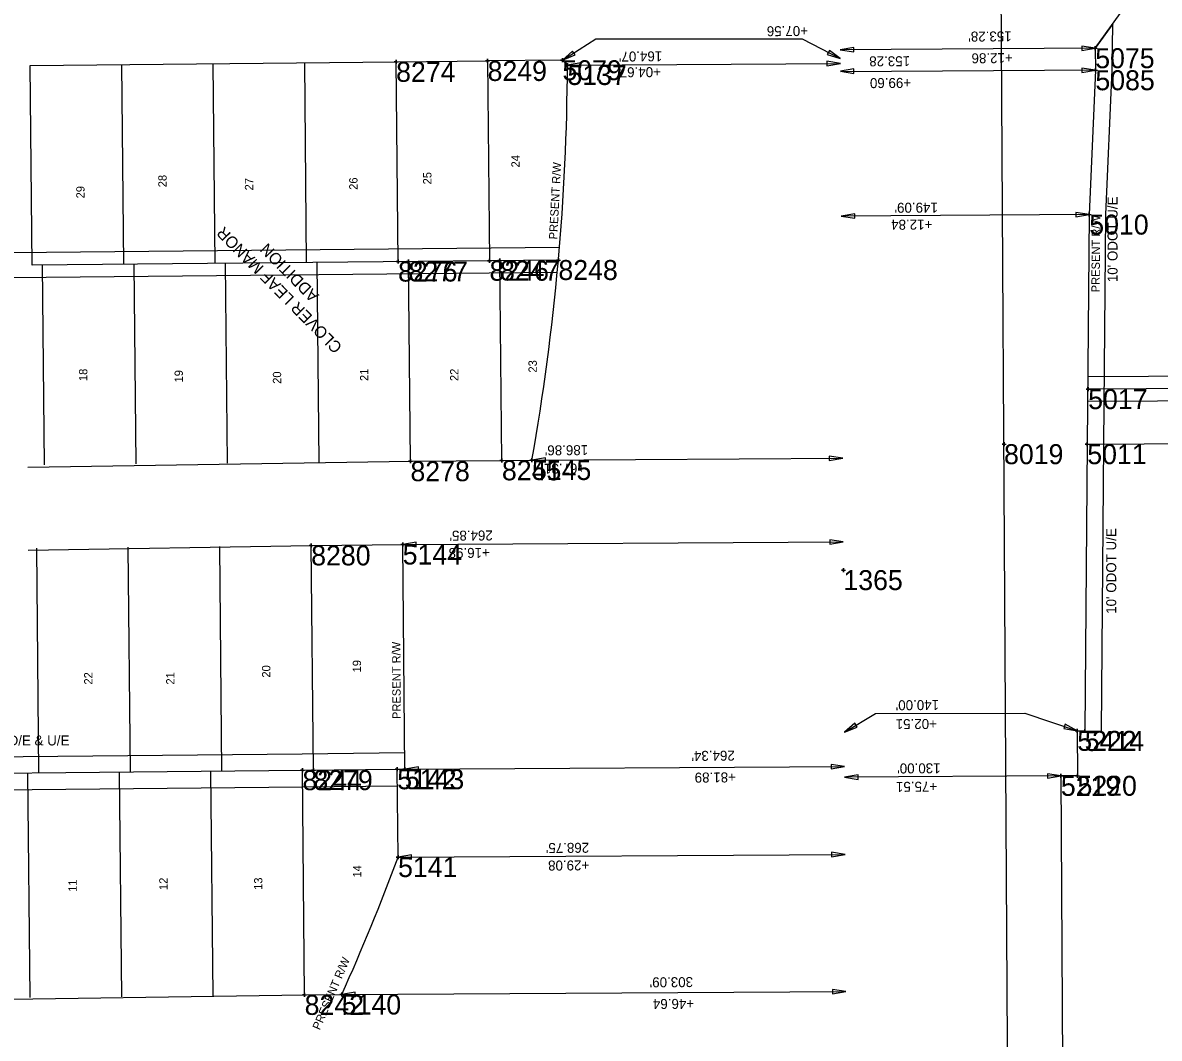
# Model space of a CAD drawing. Extents: x 2145146 to 2158053, y 137507 to 150829.
# Drawn here: x 2150322 to 2151005, y 144238 to 144848 of the extents above; entities that cross this region are included whole.
import ezdxf

# ---------------------------------------------------------------- set-up
doc = ezdxf.new("R2010")
doc.units = 0
for name, color, linetype in [('ALIGN_Cogo Points', 7, 'Continuous'), ('ALIGN_ROW Dimension', 7, 'Continuous'), ('ALIGN_ROW Line', 7, 'Continuous'), ('ALIGN_ROW Text', 7, 'Continuous'), ('PLSS_Block Line', 7, 'Continuous'), ('PLSS_Easement', 7, 'Continuous'), ('PLSS_Lot Line', 7, 'Continuous'), ('PLSS_Property Line', 7, 'Continuous'), ('PLSS_Section Line', 7, 'Continuous'), ('PLSS_Text', 7, 'Continuous'), ('PLSS_Text_TURNED OFF', 7, 'Continuous')]:
    doc.layers.add(name, color=color, linetype=linetype)

# ---------------------------------------------------------------- blocks, each defined once
blk = doc.blocks.new('Arrowhd')
at = {"layer": 'PLSS_Property Line'}
blk.add_lwpolyline([(0.125, -0.021), (0.125, 0.021), (0, 0)], close=True, dxfattribs=at)

msp = doc.modelspace()

# ---------------------------------------------------------------- linework, layer by layer
at = {"layer": 'ALIGN_Cogo Points'}
for points in [[(2150966.92, 144832.96), (2150966.92, 144834.16), (2150966.92, 144832.96), (2150965.72, 144832.96), (2150966.92, 144832.96), (2150966.92, 144831.76), (2150966.92, 144832.96), (2150968.12, 144832.96)], [(2150546.63, 144824.75), (2150546.63, 144825.95), (2150546.63, 144824.75), (2150545.43, 144824.75), (2150546.63, 144824.75), (2150546.63, 144823.55), (2150546.63, 144824.75), (2150547.83, 144824.75)], [(2150601.63, 144825.29), (2150601.63, 144826.49), (2150601.63, 144825.29), (2150600.43, 144825.29), (2150601.63, 144825.29), (2150601.63, 144824.09), (2150601.63, 144825.29), (2150602.83, 144825.29)], [(2150646.61, 144825.73), (2150646.61, 144826.93), (2150646.61, 144825.73), (2150645.41, 144825.73), (2150646.61, 144825.73), (2150646.61, 144824.53), (2150646.61, 144825.73), (2150647.81, 144825.73)], [(2150649.63, 144822.87), (2150649.63, 144824.07), (2150649.63, 144822.87), (2150648.43, 144822.87), (2150649.63, 144822.87), (2150649.63, 144821.67), (2150649.63, 144822.87), (2150650.83, 144822.87)], [(2150967.01, 144819.7), (2150967.01, 144820.9), (2150967.01, 144819.7), (2150965.81, 144819.7), (2150967.01, 144819.7), (2150967.01, 144818.5), (2150967.01, 144819.7), (2150968.21, 144819.7)], [(2150963.34, 144732.92), (2150963.34, 144734.12), (2150963.34, 144732.92), (2150962.14, 144732.92), (2150963.34, 144732.92), (2150963.34, 144731.72), (2150963.34, 144732.92), (2150964.54, 144732.92)], [(2150547.81, 144704.67), (2150547.81, 144705.87), (2150547.81, 144704.67), (2150546.61, 144704.67), (2150547.81, 144704.67), (2150547.81, 144703.47), (2150547.81, 144704.67), (2150549.01, 144704.67)], [(2150554.08, 144704.73), (2150554.08, 144705.93), (2150554.08, 144704.73), (2150552.88, 144704.73), (2150554.08, 144704.73), (2150554.08, 144703.53), (2150554.08, 144704.73), (2150555.28, 144704.73)], [(2150602.8, 144705.21), (2150602.8, 144706.41), (2150602.8, 144705.21), (2150601.6, 144705.21), (2150602.8, 144705.21), (2150602.8, 144704.01), (2150602.8, 144705.21), (2150604, 144705.21)], [(2150609.08, 144705.27), (2150609.08, 144706.47), (2150609.08, 144705.27), (2150607.88, 144705.27), (2150609.08, 144705.27), (2150609.08, 144704.07), (2150609.08, 144705.27), (2150610.28, 144705.27)], [(2150644.2, 144705.62), (2150644.2, 144706.82), (2150644.2, 144705.62), (2150643, 144705.62), (2150644.2, 144705.62), (2150644.2, 144704.42), (2150644.2, 144705.62), (2150645.4, 144705.62)], [(2150962.68, 144627.99), (2150962.68, 144629.19), (2150962.68, 144627.99), (2150961.48, 144627.99), (2150962.68, 144627.99), (2150962.68, 144626.79), (2150962.68, 144627.99), (2150963.88, 144627.99)], [(2150912.09, 144594.9), (2150912.09, 144596.1), (2150912.09, 144594.9), (2150910.89, 144594.9), (2150912.09, 144594.9), (2150912.09, 144593.7), (2150912.09, 144594.9), (2150913.29, 144594.9)], [(2150962.14, 144594.9), (2150962.14, 144596.1), (2150962.14, 144594.9), (2150960.94, 144594.9), (2150962.14, 144594.9), (2150962.14, 144593.7), (2150962.14, 144594.9), (2150963.34, 144594.9)], [(2150610.25, 144585.19), (2150610.25, 144586.39), (2150610.25, 144585.19), (2150609.05, 144585.19), (2150610.25, 144585.19), (2150610.25, 144583.99), (2150610.25, 144585.19), (2150611.45, 144585.19)], [(2150628.26, 144585.37), (2150628.26, 144586.57), (2150628.26, 144585.37), (2150627.06, 144585.37), (2150628.26, 144585.37), (2150628.26, 144584.17), (2150628.26, 144585.37), (2150629.46, 144585.37)], [(2150555.25, 144584.65), (2150555.25, 144585.85), (2150555.25, 144584.65), (2150554.05, 144584.65), (2150555.25, 144584.65), (2150555.25, 144583.45), (2150555.25, 144584.65), (2150556.45, 144584.65)], [(2150495.58, 144534.03), (2150495.58, 144535.23), (2150495.58, 144534.03), (2150494.38, 144534.03), (2150495.58, 144534.03), (2150495.58, 144532.83), (2150495.58, 144534.03), (2150496.78, 144534.03)], [(2150550.58, 144534.57), (2150550.58, 144535.77), (2150550.58, 144534.57), (2150549.38, 144534.57), (2150550.58, 144534.57), (2150550.58, 144533.37), (2150550.58, 144534.57), (2150551.78, 144534.57)], [(2150815.53, 144519.19), (2150815.53, 144520.39), (2150815.53, 144519.19), (2150814.33, 144519.19), (2150815.53, 144519.19), (2150815.53, 144517.99), (2150815.53, 144519.19), (2150816.73, 144519.19)], [(2150956.11, 144422.54), (2150956.11, 144423.74), (2150956.11, 144422.54), (2150954.91, 144422.54), (2150956.11, 144422.54), (2150956.11, 144421.34), (2150956.11, 144422.54), (2150957.31, 144422.54)], [(2150960.63, 144422.47), (2150960.63, 144423.67), (2150960.63, 144422.47), (2150959.43, 144422.47), (2150960.63, 144422.47), (2150960.63, 144421.27), (2150960.63, 144422.47), (2150961.83, 144422.47)], [(2150490.32, 144398.88), (2150490.32, 144400.08), (2150490.32, 144398.88), (2150489.12, 144398.88), (2150490.32, 144398.88), (2150490.32, 144397.68), (2150490.32, 144398.88), (2150491.52, 144398.88)], [(2150496.9, 144398.94), (2150496.9, 144400.14), (2150496.9, 144398.94), (2150495.7, 144398.94), (2150496.9, 144398.94), (2150496.9, 144397.74), (2150496.9, 144398.94), (2150498.1, 144398.94)], [(2150547.29, 144399.44), (2150547.29, 144400.64), (2150547.29, 144399.44), (2150546.09, 144399.44), (2150547.29, 144399.44), (2150547.29, 144398.24), (2150547.29, 144399.44), (2150548.49, 144399.44)], [(2150551.9, 144399.48), (2150551.9, 144400.68), (2150551.9, 144399.48), (2150550.7, 144399.48), (2150551.9, 144399.48), (2150551.9, 144398.28), (2150551.9, 144399.48), (2150553.1, 144399.48)], [(2150946.27, 144395.48), (2150946.27, 144396.68), (2150946.27, 144395.48), (2150945.07, 144395.48), (2150946.27, 144395.48), (2150946.27, 144394.28), (2150946.27, 144395.48), (2150947.47, 144395.48)], [(2150956.27, 144395.54), (2150956.27, 144396.74), (2150956.27, 144395.54), (2150955.07, 144395.54), (2150956.27, 144395.54), (2150956.27, 144394.34), (2150956.27, 144395.54), (2150957.47, 144395.54)], [(2150547.81, 144346.65), (2150547.81, 144347.85), (2150547.81, 144346.65), (2150546.61, 144346.65), (2150547.81, 144346.65), (2150547.81, 144345.45), (2150547.81, 144346.65), (2150549.01, 144346.65)], [(2150491.64, 144263.79), (2150491.64, 144264.99), (2150491.64, 144263.79), (2150490.44, 144263.79), (2150491.64, 144263.79), (2150491.64, 144262.59), (2150491.64, 144263.79), (2150492.84, 144263.79)], [(2150513.97, 144264.01), (2150513.97, 144265.21), (2150513.97, 144264.01), (2150512.77, 144264.01), (2150513.97, 144264.01), (2150513.97, 144262.81), (2150513.97, 144264.01), (2150515.17, 144264.01)]]:
    msp.add_lwpolyline(points, dxfattribs=at)
at = {"layer": 'ALIGN_ROW Dimension'}
for points in [[(2150646.61, 144825.73), (2150666.76, 144838.62), (2150790.78, 144838.62)], [(2150790.78, 144838.62), (2150813.68, 144826.73)], [(2150966.92, 144832.96), (2150813.65, 144832.04)], [(2150649.63, 144822.87), (2150813.7, 144823.85)], [(2150967.01, 144819.7), (2150813.73, 144818.78)], [(2150963.34, 144732.92), (2150814.25, 144732.02)], [(2150628.26, 144585.35), (2150815.12, 144586.47)], [(2150550.59, 144534.57), (2150815.43, 144536.16)], [(2150816.1, 144421.7), (2150834.77, 144433.03), (2150924.67, 144433.22), (2150956.11, 144422.54)], [(2150551.9, 144399.48), (2150816.24, 144401.07)], [(2150946.27, 144395.48), (2150816.28, 144394.69)], [(2150547.81, 144346.65), (2150816.56, 144348.27)], [(2150513.97, 144264.01), (2150817.05, 144265.83)]]:
    msp.add_lwpolyline(points, dxfattribs=at)
at = {"layer": 'ALIGN_ROW Line'}
for points in [[(2150966.92, 144832.96), (2150967.01, 144819.7), (2150963.34, 144732.92), (2150962.14, 144594.9), (2150960.63, 144422.47), (2150956.11, 144422.54), (2150956.27, 144395.54), (2150946.27, 144395.48), (2150947.31, 144222.48), (2150964.59, 144027.13), (2150968.98, 143967.36)], [(2150649.63, 144822.87), (2150646.61, 144825.73), (2150601.63, 144825.29)], [(2150610.25, 144585.19), (2150628.26, 144585.37)], [(2150547.81, 144346.65), (2150547.29, 144399.44), (2150551.9, 144399.48), (2150550.58, 144534.57)], [(2150491.64, 144263.79), (2150513.97, 144264.01)]]:
    msp.add_lwpolyline(points, dxfattribs=at)
for radius, start, end in [(1397.39, 349.964, 359.75306), (1382.39, 335.88153, 339.58352)]:
    msp.add_arc((2149252.26, 144828.89), radius, start, end, dxfattribs=at)
at = {"layer": 'PLSS_Block Line'}
for points in [[(2150326.69, 144822.6), (2150546.63, 144824.75), (2150601.63, 144825.29)], [(2150325.15, 144581.16), (2150555.25, 144584.65), (2150610.25, 144585.19), (2150628.26, 144585.35)], [(2150325.45, 144531.16), (2150495.6, 144534.03), (2150550.58, 144534.57)], [(2150273.6, 144260.64), (2150491.64, 144263.79), (2150513.97, 144264.01)]]:
    msp.add_lwpolyline(points, dxfattribs=at)
at = {"layer": 'PLSS_Easement'}
msp.add_lwpolyline([(2150960.63, 144422.47), (2150970.63, 144422.34), (2150972.14, 144594.95), (2150973.34, 144732.98), (2150977.02, 144819.89), (2150977.41, 144847.56), (2150966.92, 144832.96), (2150967.01, 144819.7), (2150963.34, 144732.92), (2150962.14, 144594.9)], close=True, dxfattribs=at)
for points in [[(2150644.84, 144713.12), (2150253.96, 144709.3)], [(2150643.51, 144698.11), (2150254.06, 144694.3)], [(2150966.29, 143960.36), (2151023.92, 143938.26), (2151215.08, 143953.41), (2151215.03, 144214.86), (2151144.43, 144295.52), (2151144.45, 144636.46), (2150962.64, 144635.49)], [(2150968.98, 143967.36), (2151025.02, 143945.87), (2151207.58, 143960.33), (2151207.53, 144212.04), (2151136.93, 144292.7), (2151136.95, 144628.92), (2150962.68, 144627.99)], [(2150971.66, 143974.36), (2151026.12, 143953.49), (2151200.08, 143967.26), (2151200.03, 144209.22), (2151129.43, 144289.88), (2151129.45, 144621.38), (2150962.72, 144620.49)], [(2149839.62, 144402.51), (2150490.22, 144408.84), (2150551.8, 144409.48)], [(2149839.81, 144382.51), (2150490.41, 144388.84), (2150547.39, 144389.44)]]:
    msp.add_lwpolyline(points, dxfattribs=at)
at = {"layer": 'PLSS_Lot Line'}
for points in [[(2150601.64, 144825.29), (2150602.8, 144705.21)], [(2150327.86, 144702.52), (2150326.69, 144822.6)], [(2150382.86, 144703.06), (2150381.68, 144823.14)], [(2150437.86, 144703.6), (2150436.68, 144823.67)], [(2150492.85, 144704.13), (2150491.68, 144824.21)], [(2150547.83, 144704.67), (2150546.65, 144824.75)], [(2150644.2, 144705.62), (2150327.86, 144702.52)], [(2150335.31, 144582.5), (2150334.13, 144702.58)], [(2150390.31, 144583.04), (2150389.13, 144703.12)], [(2150445.3, 144583.58), (2150444.13, 144703.66)], [(2150500.3, 144584.12), (2150499.13, 144704.2)], [(2150555.25, 144584.65), (2150554.08, 144704.73)], [(2150610.25, 144585.19), (2150609.08, 144705.27)], [(2150331.91, 144397.33), (2150330.59, 144532.42)], [(2150386.91, 144397.87), (2150385.59, 144532.96)], [(2150441.91, 144398.41), (2150440.58, 144533.49)], [(2150496.9, 144398.94), (2150495.58, 144534.03)], [(2149839.72, 144392.51), (2150490.32, 144398.84), (2150547.29, 144399.44)], [(2150326.65, 144262.18), (2150325.32, 144397.26)], [(2150381.64, 144262.71), (2150380.32, 144397.8)], [(2150436.64, 144263.25), (2150435.32, 144398.34)], [(2150491.64, 144263.79), (2150490.31, 144398.88)]]:
    msp.add_lwpolyline(points, dxfattribs=at)
at = {"layer": 'PLSS_Property Line'}
for points in [[(2150966.92, 144832.96), (2151003.22, 144883.54), (2151198.4, 144884.72), (2151198.4, 144884.72)], [(2150962.14, 144594.9), (2151236.67, 144596.48)]]:
    msp.add_lwpolyline(points, dxfattribs=at)
at = {"layer": 'PLSS_Section Line'}
msp.add_lwpolyline([(2150921.68, 142997.28), (2150905.82, 145638.98)], dxfattribs=at)

# ---------------------------------------------------------------- block references
at = {"layer": 'ALIGN_ROW Dimension'}
for p, xscale, yscale, rotation in [((2150813.64, 144832.04), 65, 65, 0.2668843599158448), ((2150966.92, 144832.96), 65.00000000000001, 64.99999999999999, -179.65177652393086), ((2150646.61, 144825.73), 65, 65, 32.59627850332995), ((2150813.7, 144823.85), 65.00000000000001, 64.99999999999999, -179.65177652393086), ((2150813.68, 144826.73), 64.99999999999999, 65.00000000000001, 152.57083784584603), ((2150649.62, 144822.87), 65, 65, 0.2668843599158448), ((2150813.71, 144819.18), 65, 65, 0.2668843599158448), ((2150967.01, 144819.7), 65.00000000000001, 64.99999999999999, -179.65177652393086), ((2150814.24, 144732.03), 65, 65, 0.2668843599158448), ((2150963.34, 144732.92), 65.00000000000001, 64.99999999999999, -179.65177652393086), ((2150628.25, 144585.37), 65, 65, 0.2668843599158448), ((2150815.12, 144586.47), 65.00000000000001, 64.99999999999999, -179.65177652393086), ((2150550.58, 144534.57), 65, 65, 0.2668843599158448), ((2150815.43, 144536.16), 65.00000000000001, 64.99999999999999, -179.65177652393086), ((2150816.1, 144421.7), 65, 65, 31.523768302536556), ((2150956.11, 144422.54), 65, 65, 160.74085774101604), ((2150816.24, 144401.07), 65.00000000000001, 64.99999999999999, -179.65177652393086), ((2150551.89, 144399.48), 65, 65, 0.2668843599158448), ((2150816.26, 144394.7), 65, 65, 0.2668843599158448), ((2150946.27, 144395.48), 65.00000000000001, 64.99999999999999, -179.65177652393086), ((2150547.79, 144346.66), 65, 65, 0.2668843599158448), ((2150816.56, 144348.27), 65.00000000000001, 64.99999999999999, -179.65177652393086), ((2150513.95, 144264.01), 65, 65, 0.2668843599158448), ((2150817.05, 144265.83), 65.00000000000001, 64.99999999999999, -179.65177652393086)]:
    msp.add_blockref('Arrowhd', p, dxfattribs=dict(at, xscale=xscale, yscale=yscale, rotation=rotation))

# ---------------------------------------------------------------- texts
at = {"layer": 'ALIGN_Cogo Points'}
for s, p in [('5075', (2150966.92, 144820.96)), ('8249', (2150601.63, 144813.29)), ('5079', (2150646.61, 144813.73)), ('8274', (2150546.63, 144812.75)), ('5137', (2150649.63, 144810.87)), ('5085', (2150967.01, 144807.7)), ('5010', (2150963.34, 144720.92)), ('8276', (2150547.81, 144692.67)), ('8277', (2150554.08, 144692.73)), ('8246', (2150602.8, 144693.21)), ('8247', (2150609.08, 144693.27)), ('8248', (2150644.2, 144693.62)), ('5017', (2150962.68, 144615.99)), ('8019', (2150912.09, 144582.9)), ('5011', (2150962.14, 144582.9)), ('8278', (2150555.25, 144572.65)), ('8245', (2150610.25, 144573.19)), ('5145', (2150628.26, 144573.37)), ('8280', (2150495.58, 144522.03)), ('5144', (2150550.58, 144522.57)), ('1365', (2150815.53, 144507.19)), ('5222', (2150956.11, 144410.54)), ('5414', (2150960.63, 144410.47)), ('8244', (2150490.32, 144386.88)), ('8279', (2150496.9, 144386.94)), ('5142', (2150547.29, 144387.44)), ('5143', (2150551.9, 144387.48)), ('5219', (2150946.27, 144383.48)), ('5220', (2150956.27, 144383.54)), ('5141', (2150547.81, 144334.65)), ('8242', (2150491.64, 144251.79)), ('5140', (2150513.97, 144252.01))]:
    msp.add_text(s, height=12, dxfattribs=at).set_placement(p)
at = {"layer": 'ALIGN_ROW Dimension'}
for s, p in [('+07.56', (2150794.22, 144846.33)), ("153.28'", (2150916.66, 144843.11)), ("164.07'", (2150706.62, 144831.11)), ('153.28', (2150855.59, 144828.2)), ('+12.86', (2150917.31, 144830.06)), ('+04.67', (2150705.81, 144821.64)), ('+99.60', (2150856.23, 144815.15)), ("149.09'", (2150872.32, 144740.19)), ('+12.84', (2150868.98, 144729.96)), ("186.86'", (2150662.06, 144594.34)), ('+67.31', (2150660.28, 144583.28)), ("264.85'", (2150604.74, 144543.05)), ('+16.98', (2150602.97, 144532.61)), ("140.00'", (2150873.02, 144441.12)), ('+02.51', (2150871.72, 144429.73)), ("264.34'", (2150750.23, 144410.65)), ("130.00'", (2150873.93, 144403.11)), ('+81.89', (2150750.87, 144397.6)), ('+75.51', (2150871.89, 144392.02)), ("268.75'", (2150662.67, 144355.29)), ('+29.08', (2150662.74, 144344.71)), ("303.09'", (2150725.12, 144274.53)), ('+46.64', (2150725.76, 144261.48))]:
    msp.add_text(s, height=6, rotation=180.3718, dxfattribs=at).set_placement(p)
at = {"layer": 'ALIGN_ROW Text'}
for rotation, p in [(87.05002, (2150643.49, 144717.93)), (89.59405, (2150969.59, 144686.2)), (90.22753, (2150549.41, 144429.68)), (66.80225, (2150500.7, 144242.35))]:
    msp.add_text('PRESENT R/W', height=5, rotation=rotation, dxfattribs=at).set_placement(p)
at = {"layer": 'PLSS_Text'}
for s, height, p in [('24', 5, (2150620.91, 144761.29)), ('25', 5, (2150567.87, 144751.09)), ('28 ', 5, (2150408.65, 144749.37)), ('27', 5, (2150460.72, 144747.49)), ('26', 5, (2150523.43, 144747.83)), ('29', 5, (2150359.34, 144742.69)), ("10' ODOT U/E", 6, (2150980.34, 144692.31)), ('23', 5, (2150631.21, 144637.96)), ('18', 5, (2150361.01, 144632.86)), ('19', 5, (2150418.44, 144632.03)), ('20', 5, (2150477.54, 144631.2)), ('21', 5, (2150529.97, 144632.86)), ('22', 5, (2150584.08, 144632.86)), ("10' ODOT U/E", 6, (2150979.54, 144492.91)), ('19', 5, (2150525.56, 144457.72)), ('22', 5, (2150364.08, 144450.38)), ('21', 5, (2150413.36, 144450.38)), ('20', 5, (2150471.03, 144454.57)), ('14', 5, (2150525.7, 144334.36)), ('12', 5, (2150409.23, 144326.87)), ('13', 5, (2150466.24, 144326.93)), ('11', 5, (2150354.66, 144325.74))]:
    msp.add_text(s, height=height, rotation=90, dxfattribs=at).set_placement(p)
msp.add_text("20' D/E & U/E", height=6, dxfattribs=at).set_placement((2150300.99, 144413.8))
at = {"layer": 'PLSS_Text_TURNED OFF'}
for s, p in [('CLOVER LEAF MANOR', (2150514.71, 144653.7)), ('ADDITION', (2150500.69, 144684.52))]:
    msp.add_text(s, height=7, rotation=134.65653, dxfattribs=at).set_placement(p)

doc.saveas('drawing.dxf')
